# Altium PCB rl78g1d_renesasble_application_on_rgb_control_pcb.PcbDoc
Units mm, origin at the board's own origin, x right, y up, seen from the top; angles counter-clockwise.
Board outline 75 x 60 mm, 2 copper layers (Top Layer, Bottom Layer); 18 components, 15 nets, 66 pads, 8 vias.
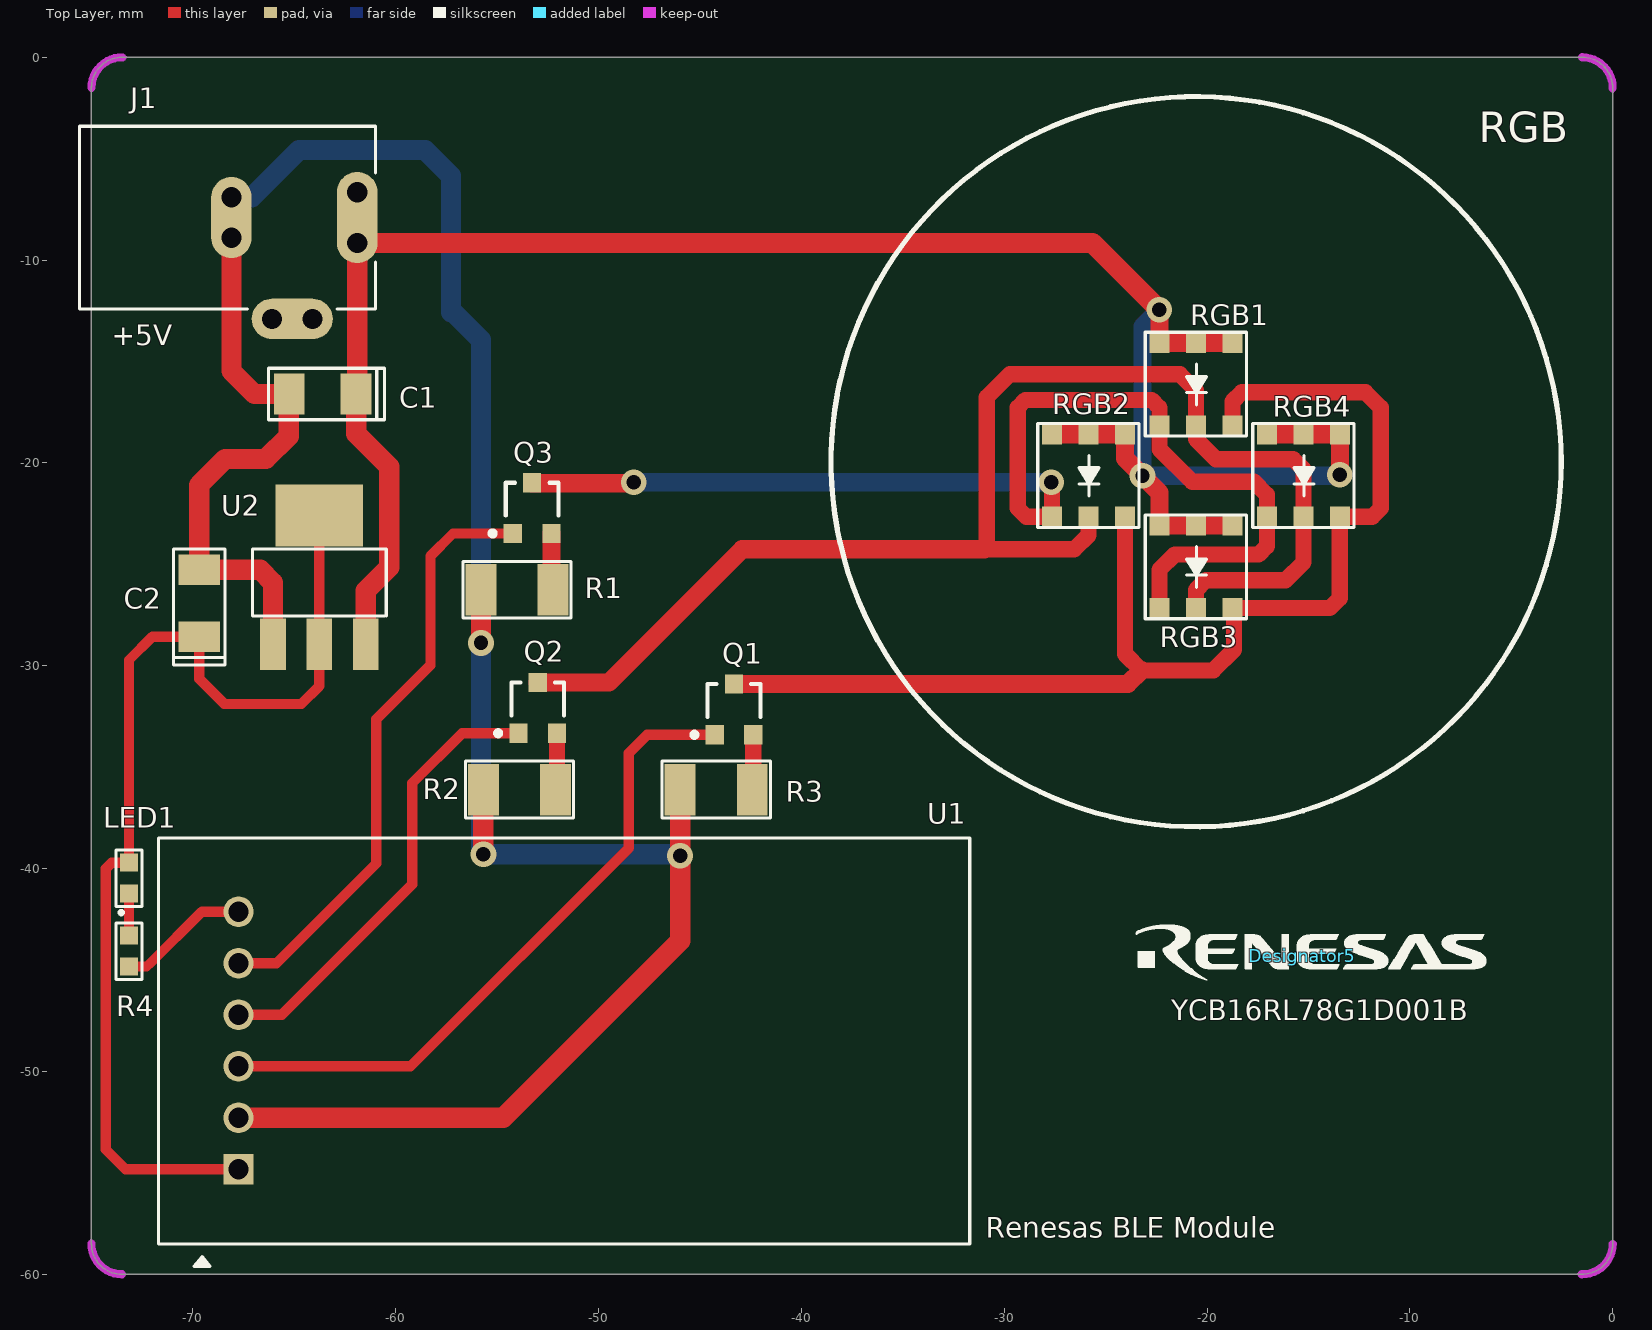
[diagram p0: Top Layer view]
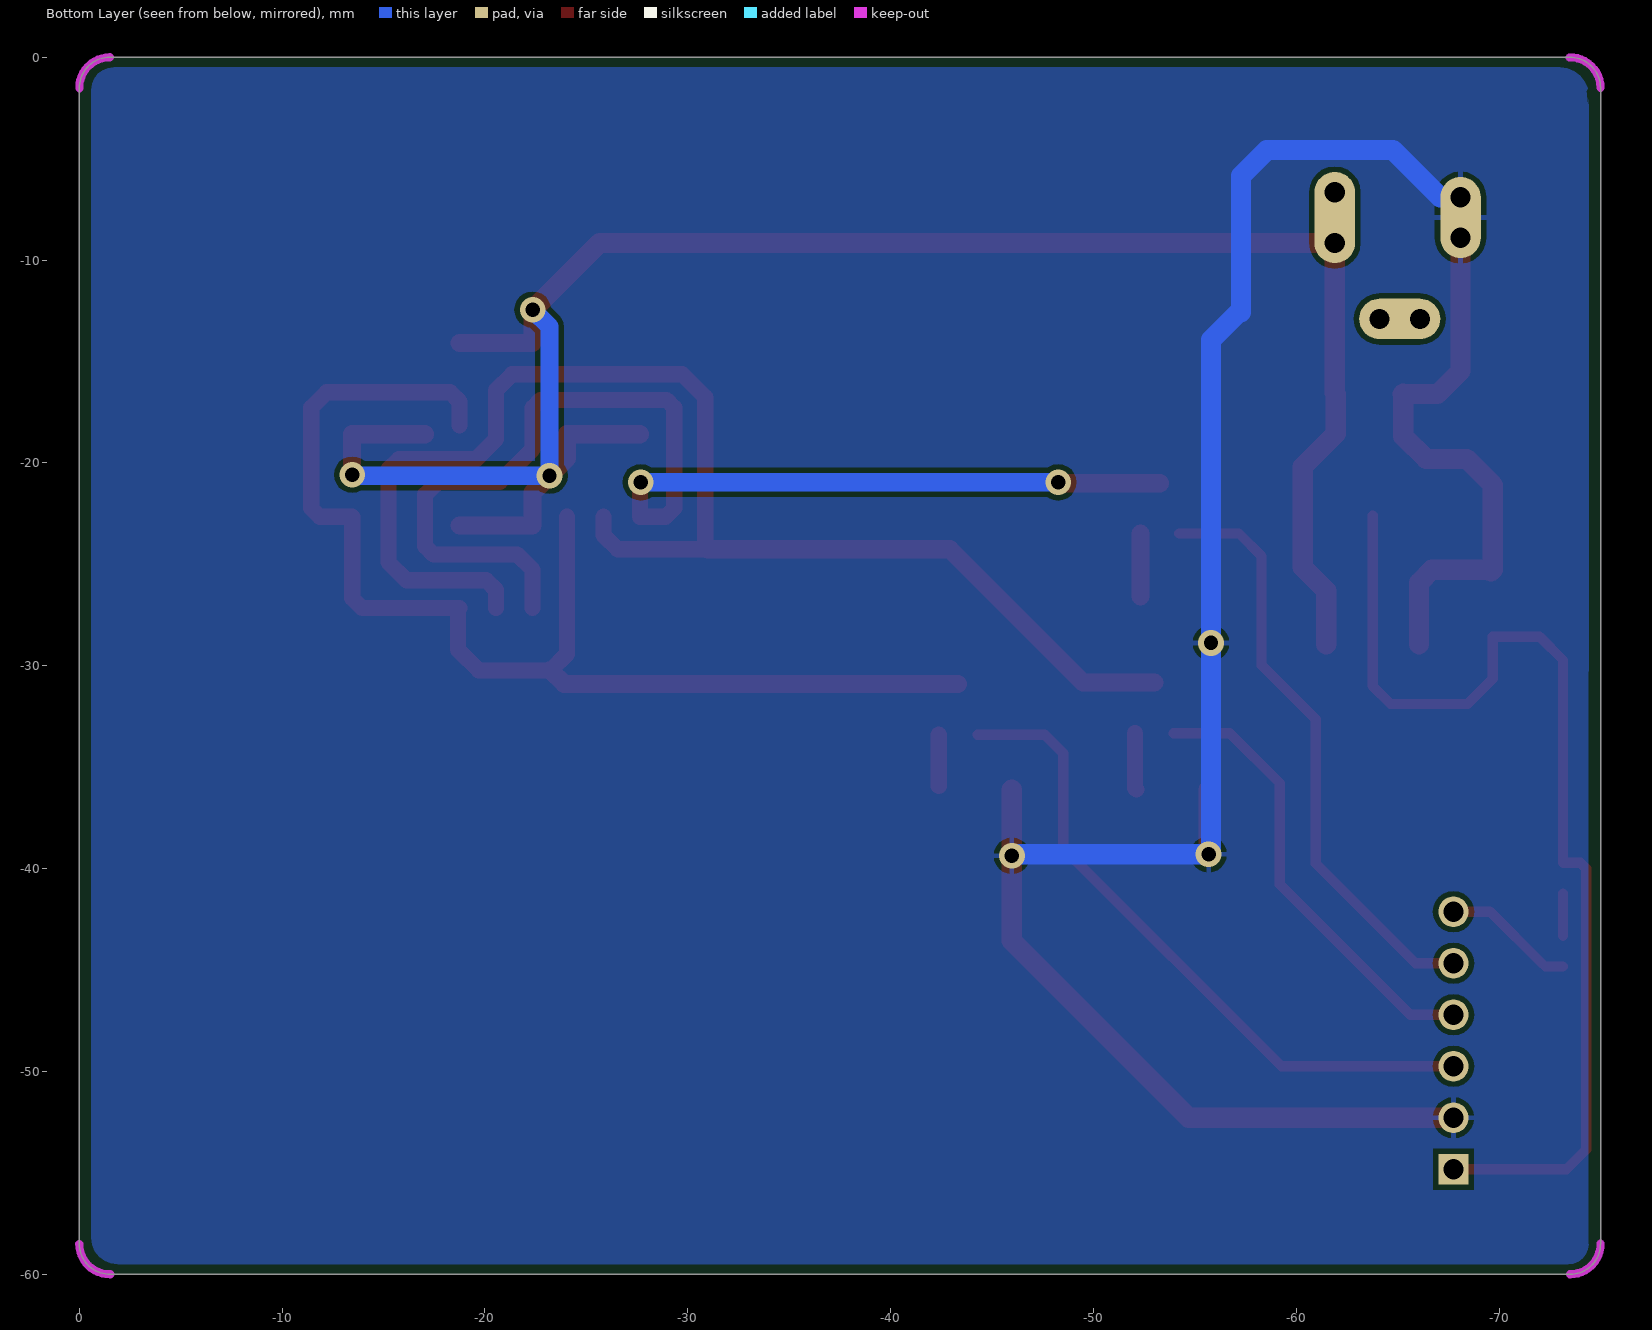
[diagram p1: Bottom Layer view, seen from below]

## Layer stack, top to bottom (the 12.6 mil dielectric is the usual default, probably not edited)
Top Layer: signal copper 0.0356
Dielectric: dielectric 0.32, FR-4, Dk 4.8
Bottom Layer: signal copper 0.0356

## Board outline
-73.5,-60 cw(c-73.5,-58.5) -75,-58.477 -75,-1.5 cw(c-73.5,-1.5) -73.477,0 -1.5,0 cw(c-1.5,-1.5) 0,-1.523 0,-58.5 cw(c-1.5,-58.5) -1.523,-60

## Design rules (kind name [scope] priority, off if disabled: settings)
Clearance [All] p1: gap=0.254
ComponentClearance [All] p1: gap=0.254 collisioncheckmode=3 verticalgap=0.254
PolygonConnect [All] p1: connectstyle=Relief reliefconductorwidth=0.254 reliefentries=4 polygonreliefangle="90 Angle"
RoutingVias [All] p1: holewidth=0.711 width=1.27 viastyle="Through Hole" minholewidth=0.711 minwidth=1.27 maxholewidth=0.711 maxwidth=1.27
SolderMaskExpansion [All] p1: expansion=0.102
TestPointUsage [All] p1: valid=0 allowmultiple=FALSE
Testpoint [All] p1: side=15 testpointundercomponent=TRUE minsize=1.016 maxsize=2.54 preferedsize=1.524 minholesize=0 maxholesize=1.016 preferedholesize=0.813 testpointgrid=0.025 style=1023 order=0123456789
Width [All] p1: maxlimit=1 minlimit=0.2 preferedwidth=0.254 minimp=50.000000 maximp=50.000000 favimp=50.000000
18 further rules are at their usual default settings.

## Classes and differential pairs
component class RGB: C1 C2 J1 LED1 Q1 Q2 Q3 R1 R2 R3 R4 RGB1 RGB2 RGB3 RGB4 U1 U2

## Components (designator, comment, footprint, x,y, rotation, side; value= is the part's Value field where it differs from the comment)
C1 "10uF" E10UF -63.6,-16.6 r180 top
C2 "10uF" E10UF -69.685,-26.915 r90 top
Designator5 "Comment" "RENESAS LOGO" -15.3,-44.3 r0 top
J1 "POWER +5V" "POWER IN" -61.9,-7.9 r0 top
LED1 "LED_POWER" "LED 0603" -73.152,-40.469 r270 top
Q1 "S8050" SOT-23B -43.325,-32.15 r0 top
Q2 "S8050" SOT-23B -53,-32.075 r0 top
Q3 "S8050" SOT-23B -53.275,-22.225 r0 top
R1 "20" 1210 -54.019,-26.256 r0 top
R2 "30" 1210 -53.9,-36.1 r0 top
R3 "30" 1210 -44.2,-36.1 r0 top
R4 "1K" 0603 -73.152,-44.069 r90 top
RGB1 "RGB LED" RGB -20.547,-13.605 r0 top
RGB2 "RGB LED" RGB -25.847,-18.105 r0 top
RGB3 "RGB LED" RGB -20.547,-22.605 r0 top
RGB4 "RGB LED" RGB -15.247,-18.105 r0 top
U1 "G1D Module" "G1D Module - 6PIN" -71.7,-48.5 r180 top (schematic designator P1)
U2 "AMS1117" SOT-223 -63.768,-28.94 r0 top

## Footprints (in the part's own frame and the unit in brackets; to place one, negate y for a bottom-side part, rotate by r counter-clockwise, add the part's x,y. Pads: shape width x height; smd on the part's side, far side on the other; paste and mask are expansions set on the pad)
0603 [mil]
  rect 35x35 smd: 1(-30,0) 2(30,0)
  silkscreen extent -55,-25 55,25
1210 [mil]
  rect 60x100 smd: 1(-70,0) 2(70,0)
  silkscreen extent -105,-55 105,55
E10UF [mil]
  rect 60x80 smd: 1(-65,0) 2(65,0)
  silkscreen extent -120,-50 105,50
"G1D Module - 6PIN" [mm]
  rect 1.5x1.5 hole 1: 1(-3.95,6.325)
  round 1.5 hole 1: 2(-3.95,3.785) 3(-3.95,1.245) 4(-3.95,-1.295) 5(-3.95,-3.835) 6(-3.95,-6.375)
  silkscreen extent -40,-10 0,11.11
"LED 0603" [mil]
  rect 35x35 smd: A(-30,0) K(30,0)
  silkscreen extent -55,-25 69,25
"POWER IN" [mm]
  oval 2x4.5 all layers, no hole: 1(0,0)
  round 1.5 hole 1: 1A(0,-1.25) 1B(0,1.25) 2A(-6.2,-1) 2B(-6.2,1) 3A(-4.2,-5) 3B(-2.2,-5)
  oval 2x4 all layers, no hole: 2(-6.2,0)
  oval 4x2 all layers, no hole: 3(-3.2,-5)
  silkscreen extent -13.7,-4.5 0.9,4.5
"RENESAS LOGO" [mm]
  silkscreen extent -8.18,-1.18 9.06,1.54
RGB [mm]
  rect 1x1 smd: 1(1.8,-0.475) 2(1.8,-4.55) 3(0,-0.475) 4(0,-4.55) 5(-1.8,-0.475) 6(-1.8,-4.55)
  silkscreen extent -2.5,-5.07 2.5,0.05
SOT-23B [mm] "SOT-23; 3 Leads; Body 3.0 x 2.6 mm, inc. leads (LxW max)"
  rect 0.9x0.95 smd: 1(-0.95,-1.25) 2(0.95,-1.25) 3(0,1.25)
  silkscreen extent -2.07,-1.37 1.3,1.25
SOT-223 [mil]
  rect 50x100 smd: 1(-90,0) 2(0,0) 3(90,0)
  rect 170x120 smd: 4(0,250)
  silkscreen extent -130,55 130,185

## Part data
C1 C2: library part Cap4, "Polarity capacitor (10uF/16V)"
J1: library part PWR2.5, "Low Voltage Power Supply Connector"
LED1: library part LED2, "Typical RED, GREEN, YELLOW, AMBER GaAs LED"
Q1 Q2 Q3: library part QNPN, "NPN Bipolar Transistor"
R1 R2 R3 R4: library part RES
RGB1 RGB2 RGB3 RGB4: "Header, 10-Pin, Dual row"
U1: library part "G1D Module-6"
U2: library part S1117

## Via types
v1: diameter 1.27, hole 0.711, Top Layer to Bottom Layer, 8 vias

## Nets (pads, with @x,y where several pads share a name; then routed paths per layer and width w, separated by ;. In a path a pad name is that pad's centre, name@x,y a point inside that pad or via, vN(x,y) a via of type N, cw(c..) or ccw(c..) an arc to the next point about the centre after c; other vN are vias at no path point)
3.3V: C2.1 LED1.A U1.1 U2.2 U2.4 | length 53.3
  Top Layer w0.5: U1.1 -73.318,-54.825 -74.295,-53.848 -74.295,-40.005 -73.997,-39.707 LED1.A -73.152,-29.718 -72,-28.566 C2.1 -69.685,-30.645 -68.453,-31.877 -64.643,-31.877 -63.768,-31.002 U2.4
5.0V: C1.1 J1.1 J1.1A J1.1B RGB1.1 RGB1.3 RGB1.5 RGB2.1 RGB2.3 RGB2.5 RGB3.1 RGB3.3 RGB3.5 RGB4.1 RGB4.3 RGB4.5 U2.3 | length 103.6
  Top Layer w0.9: RGB2.5 RGB2.1 -24.047,-19.768 -22.347,-21.468 RGB3.5 RGB3.1 ; v1@-22.347,-12.451 RGB1.5 RGB1.1 ; RGB4.5 RGB4.1 v1@-13.447,-20.569
  Top Layer w1: J1.1@-62.103,-6.477 J1.1@-61.9,-6.477 ; U2.3 -61.482,-26.303 -60.325,-25.146 -60.325,-20.193 -61.949,-18.569 C1.1 -61.9,-16.551 J1.1A -25.648,-9.15 v1@-22.347,-12.451
  Bottom Layer w0.9: v1(-22.352,-12.446) -23.183,-13.277 v1(-23.183,-20.632) -13.51,-20.632 v1(-13.457,-20.579)
GND: C1.2 C2.2 J1.2 J1.2A J1.2B R1.1 R2.1 R3.1 U1.2 U2.1 | length 123.6
  Top Layer w1: C2.2@-69.6,-25.349 C2.2 ; J1.2A -68.1,-15.466 -66.966,-16.6 C1.2 -65.278,-16.573 -65.278,-18.678 -66.4,-19.8 -68.4,-19.8 -69.685,-21.085 C2.2 ; U1.2 -54.698,-52.285 -45.978,-43.565 R3.1 ; U2.1 -66.054,-25.894 -66.684,-25.264 C2.2 ; v1(-55.797,-28.873) R1.1 ; v1(-55.678,-39.295) R2.1
  Bottom Layer w1: J1.2B -67.098,-6.9 -64.77,-4.572 -58.547,-4.572 -57.277,-5.842 -57.277,-12.573 ; -57.277,-12.446 -55.797,-13.926 -55.797,-39.176 v1(-55.678,-39.295) -46.053,-39.295 v1(-45.978,-39.37)
NetJ1_3: J1.3 J1.3A J1.3B
NetLED1_K: LED1.K R4.2 | length 2.1
  Top Layer w0.5: R4.2 LED1.K
NetP1_6: R4.1 U1.6 | length 6.3
  Top Layer w0.5: R4.1 -72.291,-44.831 ; -72.114,-44.682 -69.557,-42.125 U1.6
NetQ1_2: Q1.2 R3.2 | length 2.5
  Top Layer w0.8: R3.2@-42.375,-35.925 Q1.2
NetQ1_3: Q1.3 RGB1.2 RGB2.2 RGB3.2 RGB4.2 | length 61
  Top Layer w0.8: RGB2.2 -24.047,-29.42 -23.241,-30.226 -19.685,-30.226 -18.669,-29.21 -18.669,-27.233 RGB3.2 -13.947,-27.155 -13.462,-26.67 -13.462,-22.67 RGB4.2 -11.86,-22.655 -11.43,-22.225 -11.43,-17.272 -12.192,-16.51 -18.288,-16.51 -18.747,-16.969 RGB1.2
  Top Layer w0.9: Q1.3@-43.325,-30.896 -23.911,-30.896 -23.241,-30.226
NetQ2_2: Q2.2 R2.2 | length 2.8
  Top Layer w0.8: R2.2 -52.05,-36.028 Q2.2
NetQ2_3: Q2.3 RGB1.4 RGB2.4 RGB3.4 RGB4.4 | length 69.4
  Top Layer w0.8: -30.988,-24.257 -26.543,-24.257 -25.847,-23.561 RGB2.4 ; -30.861,-24.257 -30.861,-16.764 -29.718,-15.621 -21.336,-15.621 -20.547,-16.41 -20.547,-18.823 -19.558,-19.812 -15.748,-19.812 -15.247,-20.313 RGB4.4 -15.24,-22.662 -15.24,-24.892 -16.129,-25.781 -20.066,-25.781 -20.547,-26.262 RGB3.4
  Top Layer w0.9: Q2.3 -49.494,-30.825 -42.926,-24.257 -30.988,-24.257
NetQ3_2: Q3.2 R1.2 | length 3.1
  Top Layer w0.9: R1.2@-52.325,-26.575 Q3.2
NetQ3_3: Q3.3 RGB1.6 RGB2.6 RGB3.6 RGB4.6 | length 59.9
  Top Layer w0.8: v1@-48.308,-21.003 v1(-48.26,-20.955) ; v1@-27.647,-20.994 RGB2.6 -28.907,-22.655 -29.337,-22.225 -29.337,-17.272 -28.956,-16.891 -22.733,-16.891 -22.347,-17.277 -22.347,-19.309 -20.732,-20.924 -17.684,-20.924 -17.047,-21.561 -17.047,-24.101 -17.457,-24.511 -21.59,-24.511 -22.347,-25.268 RGB3.6
  Top Layer w0.9: Q3.3@-53.275,-21.003 v1@-48.308,-21.003
  Bottom Layer w0.9: v1(-48.26,-20.955) v1(-27.686,-20.955)
PWM_B: Q1.1 U1.3 | length 33
  Top Layer w0.5: U1.3 -59.27,-49.745 -48.514,-38.989 -48.514,-34.314 -47.6,-33.4 Q1.1
PWM_G: Q3.1 U1.5 | length 29.6
  Top Layer w0.5: U1.5 -65.874,-44.665 -60.96,-39.751 -60.96,-32.639 -58.293,-29.972 -58.293,-24.593 -57.175,-23.475 Q3.1
PWM_R: Q2.1 U1.4 | length 22.5
  Top Layer w0.5: U1.4 -65.62,-47.205 -59.182,-40.767 -59.182,-35.782 -56.725,-33.325 Q2.1

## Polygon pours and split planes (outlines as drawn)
GND on Bottom Layer "Top Overlay-No Net" (solid, pour order 1000): -74.4,-2.5 -74.4,-1.9 cw(c-73,-1.9) -73,-0.5 -1.7,-0.5 cw(c-1.7,-1.6) -0.6,-1.6 -0.6,-3.7 -0.6,-58.2 cw(c-1.9,-58.2) -1.9,-59.5 -72.9,-59.5 -73.4,-59.5 cw(c-73.4,-58.5) -74.4,-58.5 -74.4,-1.8 cw(c-74.3,-1.8) -74.3,-1.7

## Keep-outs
Keep-Out Layer:
  lines w0.4: -75,-58.477 ccw(c-73.5,-58.5) -73.5,-60 ; -75,-1.5 cw(c-73.5,-1.5) -73.477,0 ; -1.523,-60 ccw(c-1.5,-58.5) 0,-58.5 ; -1.5,0 cw(c-1.5,-1.5) 0,-1.523

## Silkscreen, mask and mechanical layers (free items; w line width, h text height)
Top Overlay:
  circle w0.254: c-20.54,-19.939 r18
  text "RGB" at -6.6,-4.2 h1.5
  text "+5V" at -74,-14.2 h1
  text "YCB16RL78G1D001B" at -21.775,-47.485 h1
  text "Renesas BLE Module" at -30.9,-58.2 h1
Mechanical 1:
  lines w0.254: -78.908,-58.58 -78.4,-60.104 ; -78.908,-1.628 -78.4,-0.104 ; -78.654,-60.104 -78.146,-60.104 ; -78.654,-0.104 -78.146,-0.104 ; -78.4,-35.308 -78.4,-60.104 ; -78.4,-24.9 -78.4,-0.104 ; -77.892,-58.58 -78.4,-60.104 ; -77.892,-1.628 -78.4,-0.104 ; -75.05,2.66 -75.05,3.168 ; -73.526,2.406 -75.05,2.914 ; -73.526,3.422 -75.05,2.914 ; -42.754,2.914 -75.05,2.914 ; -32.346,2.914 -0.05,2.914 ; -1.574,2.406 -0.05,2.914 ; -1.574,3.422 -0.05,2.914 ; -0.05,2.66 -0.05,3.168
  lines w0.4: -75,-58.477 -75,-1.5 ; -73.5,-60 -1.523,-60 ; -73.477,0 -1.5,0 ; 0,-58.5 0,-1.523
  text "75 (mm)" at -42.5,1.9 h1.52
  text "60 (mm)" at -77.386,-35.054 h1.52 r90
